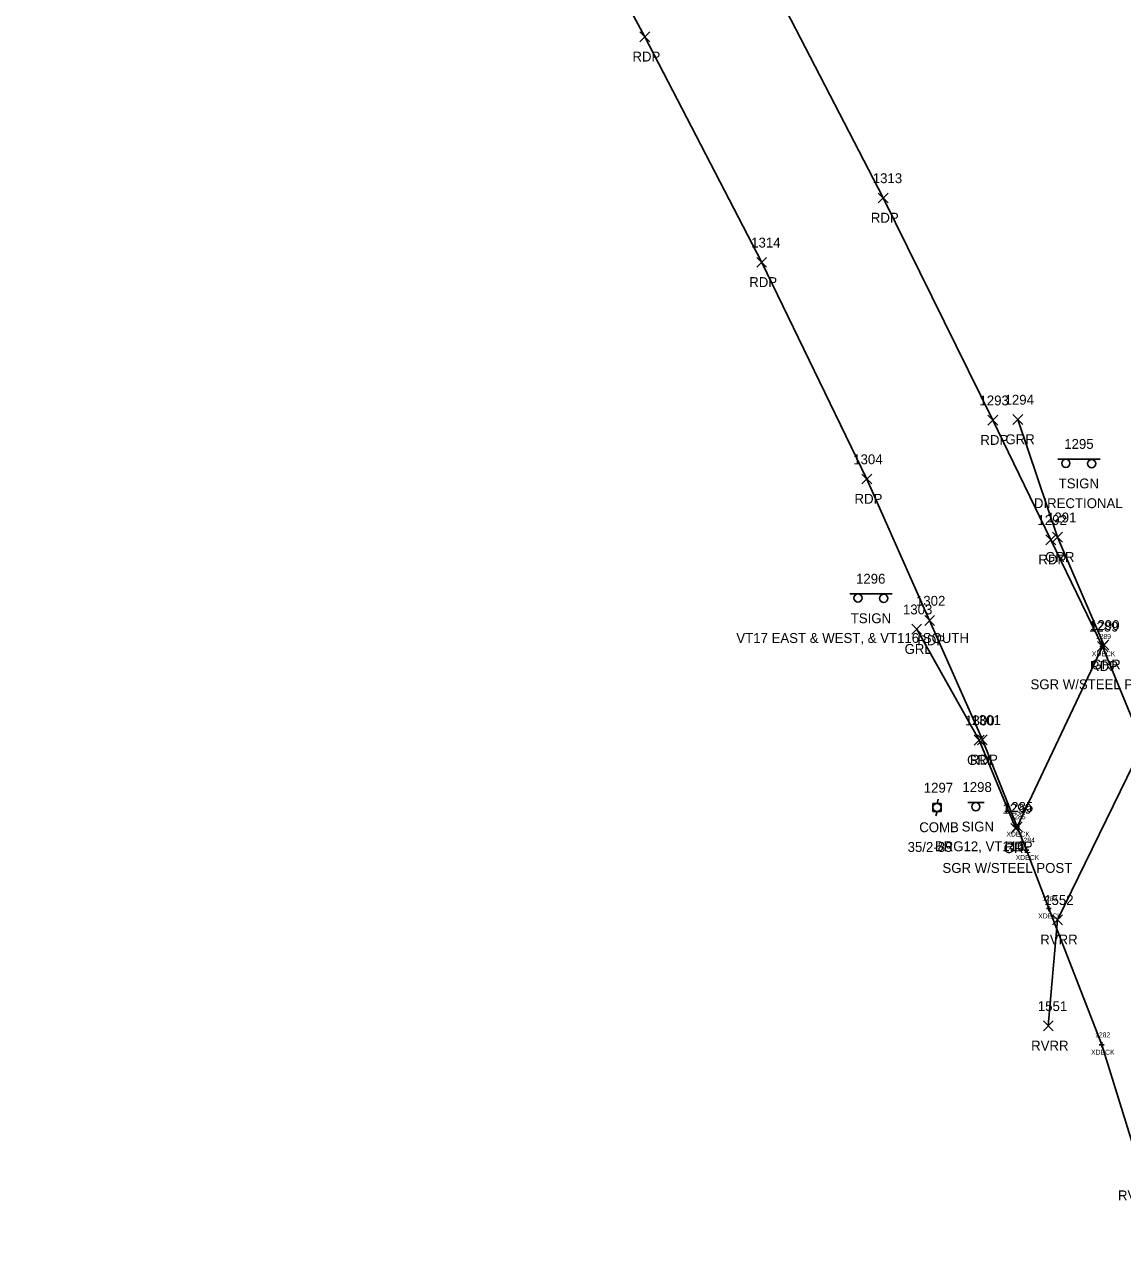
# Model space of a CAD drawing. Extents: x 1496556 to 1498241, y 599216 to 604470.
# Drawn here: x 1496982.4 to 1497204.8, y 603046.8 to 603294.3 of the extents above; entities that cross this region are included whole.
import ezdxf

# ---------------------------------------------------------------- set-up
doc = ezdxf.new("R2010")
doc.units = 0
for name, color, linetype in [('B_A', 7, 'Continuous'), ('B_I', 7, 'Continuous'), ('B_TIC', 7, 'Continuous'), ('BELB', 7, 'Continuous'), ('L_A', 7, 'Continuous'), ('L_I', 7, 'Continuous'), ('L_TIC', 7, 'Continuous'), ('LAWE', 7, 'Continuous'), ('P_A', 7, 'Continuous'), ('P_I', 7, 'Continuous'), ('P_TIC', 7, 'Continuous'), ('PET', 7, 'Continuous'), ('R_A', 7, 'Continuous'), ('R_C', 7, 'Continuous'), ('R_I', 7, 'Continuous'), ('R_TIC', 7, 'Continuous'), ('RGR', 7, 'Continuous'), ('S_A', 7, 'Continuous'), ('S_C', 7, 'Continuous'), ('S_I', 7, 'Continuous'), ('SSGN', 7, 'Continuous'), ('U_A', 7, 'Continuous'), ('U_C', 7, 'Continuous'), ('U_I', 7, 'Continuous'), ('UP', 7, 'Continuous')]:
    doc.layers.add(name, color=color, linetype=linetype)

msp = doc.modelspace()

# ---------------------------------------------------------------- linework, layer by layer
at = {"layer": 'B_TIC'}
for p, q in [((1497200.79, 603168.36), (1497200.86, 603168.36)), ((1497200.79, 603168.36), (1497200.86, 603168.36)), ((1497183.49, 603131.83), (1497183.57, 603131.83)), ((1497185.37, 603127.09), (1497185.45, 603127.09)), ((1497189.92, 603115.25), (1497190, 603115.25)), ((1497200.63, 603087.66), (1497200.71, 603087.66))]:
    msp.add_line(p, q, dxfattribs=at)
for points in [[(1497200.78, 603167.86), (1497200.78, 603168.86)], [(1497200.78, 603167.86), (1497200.78, 603168.86)], [(1497200.28, 603168.36), (1497201.28, 603168.36)], [(1497200.28, 603168.36), (1497201.28, 603168.36)], [(1497182.99, 603131.83), (1497183.99, 603131.83)], [(1497183.49, 603131.33), (1497183.49, 603132.33)], [(1497184.87, 603127.09), (1497185.87, 603127.09)], [(1497185.37, 603126.59), (1497185.37, 603127.59)], [(1497189.42, 603115.25), (1497190.42, 603115.25)], [(1497189.92, 603114.75), (1497189.92, 603115.75)], [(1497200.13, 603087.66), (1497201.13, 603087.66)], [(1497200.63, 603087.16), (1497200.63, 603088.16)]]:
    msp.add_lwpolyline(points, dxfattribs=at)
at = {"layer": 'BELB'}
for points in [[(1497213.53, 603046.79), (1497207.36, 603066.11), (1497200.63, 603087.66), (1497189.92, 603115.25), (1497185.37, 603127.09), (1497183.49, 603131.83), (1497200.78, 603168.36)], [(1497231.7, 603087.32), (1497225.58, 603104.83), (1497219.14, 603122.16), (1497211.03, 603143.32), (1497200.78, 603168.36)]]:
    msp.add_lwpolyline(points, dxfattribs=at)
at = {"layer": 'L_TIC'}
for points in [[(1497190.67, 603111.98), (1497192.67, 603113.98)], [(1497192.67, 603111.98), (1497190.67, 603113.98)], [(1497188.81, 603090.49), (1497190.81, 603092.49)], [(1497190.81, 603090.49), (1497188.81, 603092.49)]]:
    msp.add_lwpolyline(points, dxfattribs=at)
at = {"layer": 'LAWE'}
msp.add_lwpolyline([(1497189.81, 603091.49), (1497191.67, 603112.98), (1497209.98, 603150.46), (1497214.03, 603174.34), (1497209.01, 603206.37), (1497211.24, 603222.01), (1497227.45, 603268.03), (1497246.38, 603332.34), (1497269.89, 603360.04), (1497296.95, 603397.6), (1497313.57, 603422.44), (1497323.64, 603438.94), (1497334.8, 603445.38), (1497344.77, 603450.19), (1497370.1, 603467.8), (1497419.49, 603471.31), (1497456.04, 603468.84), (1497488.04, 603460.85), (1497518.38, 603461.84), (1497564.45, 603467.31)], dxfattribs=at)
at = {"layer": 'P_TIC'}
for points in [[(1497107.09, 603290.8), (1497109.09, 603292.8)], [(1497109.09, 603290.8), (1497107.09, 603292.8)], [(1497155.38, 603258.17), (1497157.38, 603260.17)], [(1497157.38, 603258.17), (1497155.38, 603260.17)], [(1497130.76, 603245.13), (1497132.76, 603247.13)], [(1497132.76, 603245.13), (1497130.76, 603247.13)], [(1497177.56, 603213.16), (1497179.56, 603215.16)], [(1497179.56, 603213.16), (1497177.56, 603215.16)], [(1497152.07, 603201.24), (1497154.07, 603203.24)], [(1497154.07, 603201.24), (1497152.07, 603203.24)], [(1497189.31, 603188.95), (1497191.31, 603190.95)], [(1497191.31, 603188.95), (1497189.31, 603190.95)], [(1497164.78, 603172.58), (1497166.78, 603174.58)], [(1497166.78, 603172.58), (1497164.78, 603174.58)], [(1497199.78, 603167.36), (1497201.78, 603169.36)], [(1497201.78, 603167.36), (1497199.78, 603169.36)], [(1497175.45, 603148.42), (1497177.45, 603150.42)], [(1497177.45, 603148.42), (1497175.45, 603150.42)], [(1497182.49, 603130.83), (1497184.49, 603132.83)], [(1497184.49, 603130.83), (1497182.49, 603132.83)]]:
    msp.add_lwpolyline(points, dxfattribs=at)
at = {"layer": 'PET'}
for points in [[(1497200.78, 603168.36), (1497190.31, 603189.95), (1497178.56, 603214.16), (1497156.38, 603259.17), (1497132.76, 603304.93), (1497107.74, 603351.81), (1497085.25, 603391.58), (1497052.51, 603451.39), (1497026.34, 603497.64), (1496978.11, 603585.44), (1496929.41, 603673.01), (1496891.52, 603741.51), (1496859.85, 603799.39), (1496832.17, 603849.95), (1496783.86, 603937.37), (1496736.46, 604023.53), (1496687.77, 604111.18), (1496657.13, 604166.72), (1496622.36, 604229.38), (1496597.22, 604275.47)], [(1497183.49, 603131.83), (1497176.45, 603149.42), (1497165.78, 603173.58), (1497153.07, 603202.24), (1497131.76, 603246.13), (1497108.09, 603291.8), (1497082.6, 603339.21), (1497060.69, 603378.6), (1497027.78, 603438.86), (1497002.63, 603483.06), (1496952.93, 603573.18), (1496904.09, 603661), (1496858.14, 603744.51), (1496836.02, 603785.33), (1496807.5, 603837.5), (1496759.38, 603924.22), (1496712.33, 604009.42), (1496662.89, 604098.73), (1496632.3, 604154.09), (1496599.03, 604214.45), (1496572.34, 604262.99)]]:
    msp.add_lwpolyline(points, dxfattribs=at)
at = {"layer": 'R_TIC'}
for points in [[(1497182.64, 603213.3), (1497184.64, 603215.3)], [(1497184.64, 603213.3), (1497182.64, 603215.3)], [(1497190.68, 603189.46), (1497192.68, 603191.46)], [(1497192.68, 603189.46), (1497190.68, 603191.46)], [(1497162.15, 603170.83), (1497164.15, 603172.83)], [(1497164.15, 603170.83), (1497162.15, 603172.83)], [(1497200.06, 603167.67), (1497202.06, 603169.67)], [(1497202.06, 603167.67), (1497200.06, 603169.67)], [(1497174.82, 603148.34), (1497176.82, 603150.34)], [(1497176.82, 603148.34), (1497174.82, 603150.34)], [(1497182.23, 603130.48), (1497184.23, 603132.48)], [(1497184.23, 603130.48), (1497182.23, 603132.48)]]:
    msp.add_lwpolyline(points, dxfattribs=at)
at = {"layer": 'RGR'}
for points in [[(1497201.06, 603168.67), (1497191.68, 603190.46), (1497183.64, 603214.3)], [(1497183.23, 603131.48), (1497175.82, 603149.34), (1497163.15, 603171.83)]]:
    msp.add_lwpolyline(points, dxfattribs=at)
at = {"layer": 'SSGN'}
for p, q in [((1497191.71, 603206.27), (1497200.31, 603206.27)), ((1497195.73, 603205.36), (1497195.73, 603205.36)), ((1497149.6, 603178.97), (1497158.2, 603178.97)), ((1497153.63, 603178.07), (1497153.63, 603178.07)), ((1497173.49, 603136.72), (1497176.82, 603136.72)), ((1497175.14, 603135.88), (1497175.14, 603135.88))]:
    msp.add_line(p, q, dxfattribs=at)
for centre in [(1497193.37, 603205.43), (1497198.59, 603205.36), (1497151.26, 603178.14), (1497156.48, 603178.07), (1497175.14, 603135.88)]:
    msp.add_circle(centre, 0.833, dxfattribs=at)
at = {"layer": 'UP'}
for p, q in [((1497167.53, 603137.38), (1497167.28, 603136.55)), ((1497166.45, 603134.88), (1497166.45, 603136.55)), ((1497166.45, 603136.55), (1497168.12, 603136.55)), ((1497168.12, 603134.88), (1497166.45, 603134.88)), ((1497167.03, 603134.05), (1497167.28, 603134.88)), ((1497167.28, 603135.72), (1497167.28, 603135.72)), ((1497168.12, 603136.55), (1497168.12, 603134.88))]:
    msp.add_line(p, q, dxfattribs=at)
msp.add_circle((1497167.28, 603135.72), 0.833, dxfattribs=at)

# ---------------------------------------------------------------- texts
at = {"layer": 'B_A'}
for p in [(1497198.63, 603166.36), (1497198.63, 603166.36), (1497181.33, 603129.83), (1497183.21, 603125.09), (1497187.76, 603113.25), (1497198.47, 603085.66)]:
    msp.add_text('XDECK', height=1, dxfattribs=at).set_placement(p)
at = {"layer": 'B_I'}
for s, p in [('1289', (1497199.43, 603169.86)), ('1289', (1497199.43, 603169.86)), ('1285', (1497182.14, 603133.33)), ('1284', (1497184.02, 603128.59)), ('1283', (1497188.57, 603116.75)), ('1282', (1497199.28, 603089.16))]:
    msp.add_text(s, height=1, dxfattribs=at).set_placement(p)
at = {"layer": 'L_A'}
for p in [(1497188.18, 603107.98), (1497186.33, 603086.49), (1497203.92, 603056.16)]:
    msp.add_text('RVRR', height=2, dxfattribs=at).set_placement(p)
at = {"layer": 'L_I'}
for s, p in [('1552', (1497188.98, 603115.98)), ('1551', (1497187.69, 603094.49))]:
    msp.add_text(s, height=2, dxfattribs=at).set_placement(p)
at = {"layer": 'P_A'}
for p in [(1497105.58, 603286.8), (1497153.87, 603254.17), (1497129.24, 603241.13), (1497176.05, 603209.16), (1497150.56, 603197.24), (1497187.8, 603184.95), (1497163.27, 603168.58), (1497198.27, 603163.36), (1497173.94, 603144.42), (1497180.98, 603126.83)]:
    msp.add_text('RDP', height=2, dxfattribs=at).set_placement(p)
at = {"layer": 'P_I'}
for s, p in [('1313', (1497154.26, 603262.17)), ('1314', (1497129.63, 603249.13)), ('1293', (1497175.87, 603217.16)), ('1304', (1497150.3, 603205.24)), ('1292', (1497187.62, 603192.95)), ('1302', (1497163.01, 603176.58)), ('1289', (1497198.08, 603171.36)), ('1301', (1497174.25, 603152.42)), ('1285', (1497180.8, 603134.83))]:
    msp.add_text(s, height=2, dxfattribs=at).set_placement(p)
at = {"layer": 'R_A'}
for s, p in [('GRR', (1497181.13, 603209.3)), ('GRR', (1497189.17, 603185.46)), ('GRL', (1497160.7, 603166.83)), ('GRR', (1497198.54, 603163.67)), ('GRL', (1497173.36, 603144.34)), ('GRL', (1497180.77, 603126.48))]:
    msp.add_text(s, height=2, dxfattribs=at).set_placement(p)
at = {"layer": 'R_C'}
for p in [(1497186.2, 603159.67), (1497168.37, 603122.48)]:
    msp.add_text('SGR W/STEEL POST', height=2, dxfattribs=at).set_placement(p)
at = {"layer": 'R_I'}
for s, p in [('1294', (1497180.95, 603217.3)), ('1291', (1497189.55, 603193.46)), ('1303', (1497160.38, 603174.83)), ('1290', (1497198.28, 603171.67)), ('1300', (1497172.96, 603152.34)), ('1299', (1497180.53, 603134.48))]:
    msp.add_text(s, height=2, dxfattribs=at).set_placement(p)
at = {"layer": 'S_A'}
for s, p in [('TSIGN', (1497191.91, 603200.35)), ('TSIGN', (1497149.8, 603173.05)), ('SIGN', (1497172.27, 603130.86))]:
    msp.add_text(s, height=2, dxfattribs=at).set_placement(p)
at = {"layer": 'S_C'}
for s, p in [('DIRECTIONAL', (1497186.89, 603196.35)), ('VT17 EAST & WEST, & VT116 SOUTH', (1497126.63, 603169.05)), ('BRG12, VT116', (1497166.84, 603126.86))]:
    msp.add_text(s, height=2, dxfattribs=at).set_placement(p)
at = {"layer": 'S_I'}
for s, p in [('1295', (1497193.04, 603208.35)), ('1296', (1497150.87, 603181.05)), ('1298', (1497172.42, 603138.86))]:
    msp.add_text(s, height=2, dxfattribs=at).set_placement(p)
at = {"layer": 'U_A'}
msp.add_text('COMB', height=2, dxfattribs=at).set_placement((1497163.67, 603130.72))
at = {"layer": 'U_C'}
msp.add_text('35/2-89', height=2, dxfattribs=at).set_placement((1497161.32, 603126.72))
at = {"layer": 'U_I'}
msp.add_text('1297', height=2, dxfattribs=at).set_placement((1497164.59, 603138.72))

doc.saveas('drawing.dxf')
